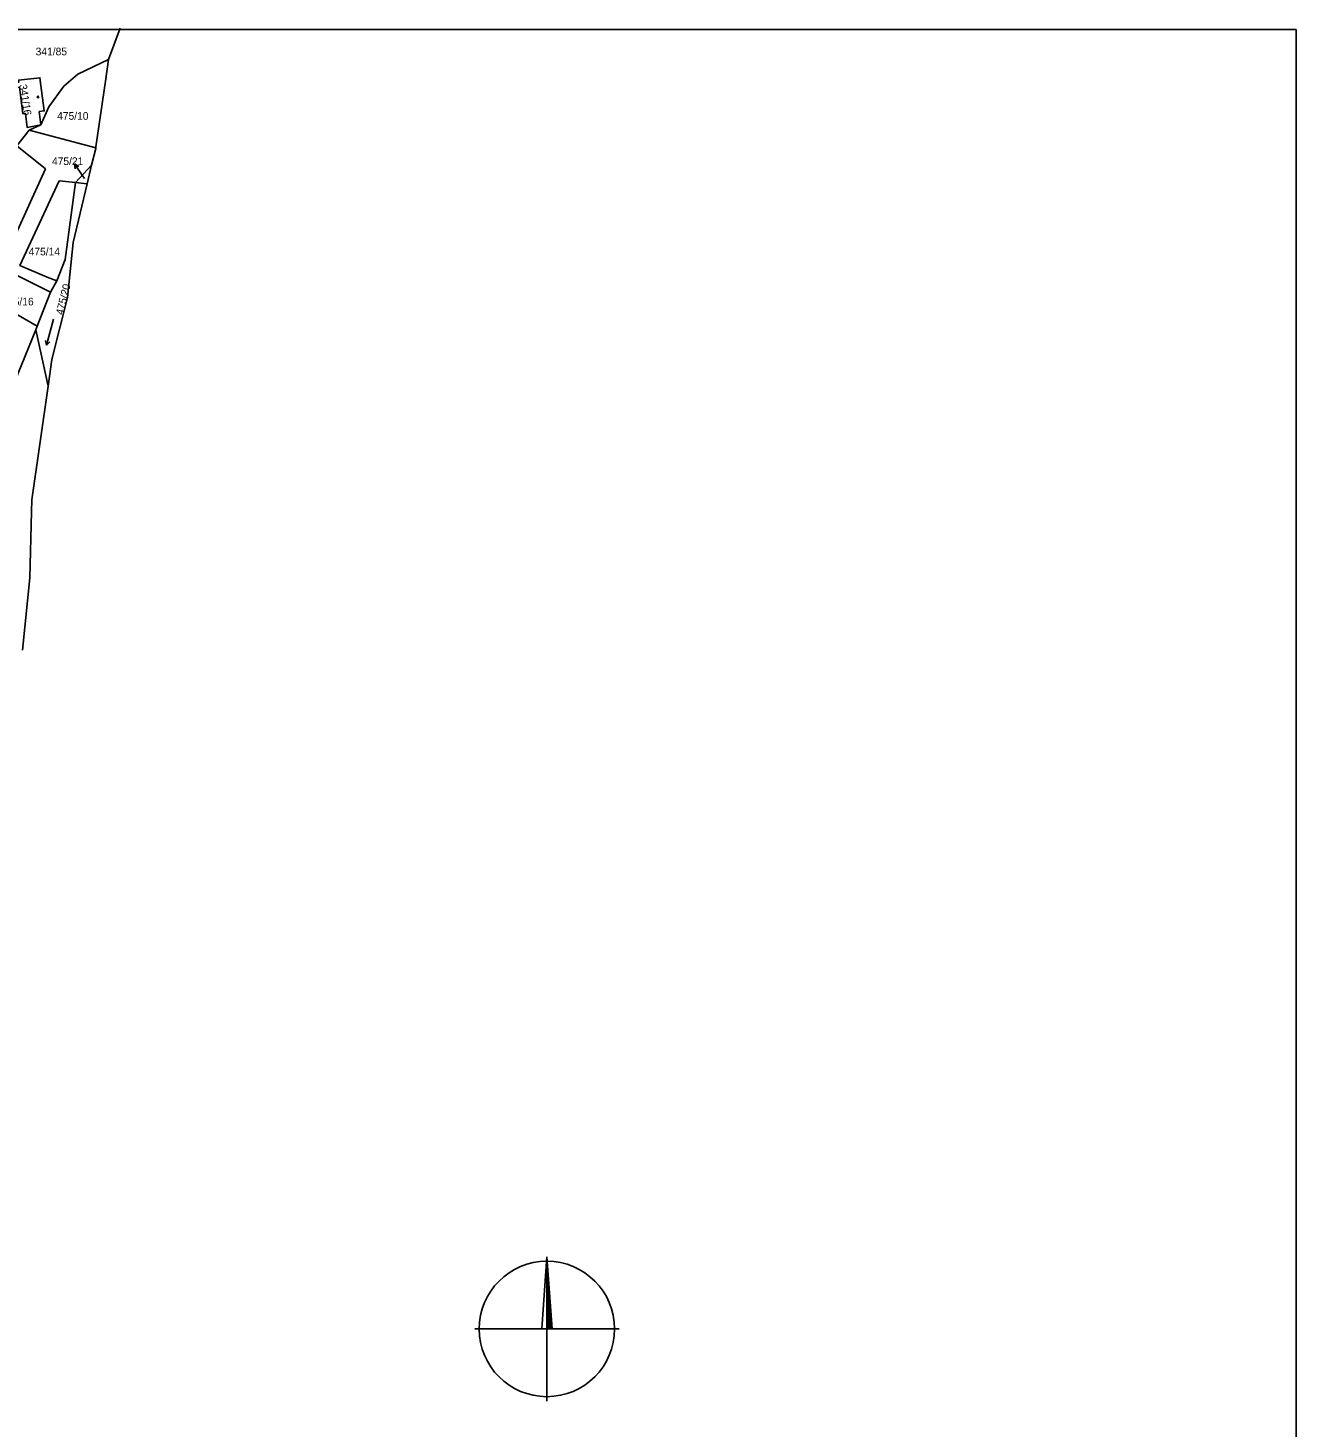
# Model space of a CAD drawing. Extents: x -558358 to -557517, y -1073786 to -1073189.
# Drawn here: x -557797.5 to -557516.5, y -1073499.8 to -1073189.7 of the extents above; entities that cross this region are included whole.
import ezdxf

# ---------------------------------------------------------------- set-up
doc = ezdxf.new("R2010")
doc.units = 0
for name, color, linetype in [('Hranice parcel', 7, 'Continuous'), ('Parcelní čísla', 7, 'Continuous'), ('Pop  PČ popisy', 7, 'Continuous'), ('Vrstva 1', 7, 'Continuous'), ('Značky budov', 7, 'Continuous'), ('Značky kultur', 7, 'Continuous')]:
    doc.layers.add(name, color=color, linetype=linetype)

msp = doc.modelspace()

# ---------------------------------------------------------------- linework, layer by layer
at = {"layer": 'Hranice parcel'}
for p, q in [((-557780.35, -1073201.52), (-557779.66, -1073196.74)), ((-557782.46, -1073216.02), (-557780.35, -1073201.52)), ((-557794.69, -1073211.15), (-557797.26, -1073212.4)), ((-557797.26, -1073212.4), (-557799.96, -1073215.86)), ((-557782.49, -1073216.26), (-557797.26, -1073212.4)), ((-557782.49, -1073216.26), (-557782.46, -1073216.02)), ((-557786.97, -1073223.95), (-557783.4, -1073220.15)), ((-557784.37, -1073224.22), (-557783.4, -1073220.15)), ((-557784.37, -1073224.22), (-557786.97, -1073223.95)), ((-557795.47, -1073255.77), (-557792.5, -1073248.24)), ((-557792.5, -1073248.24), (-557791.11, -1073245.75)), ((-557795.47, -1073255.77), (-557805.42, -1073250.06)), ((-557802.11, -1073272.13), (-557795.8, -1073256.6)), ((-557795.8, -1073256.6), (-557795.47, -1073255.77)), ((-557793.06, -1073269.04), (-557795.8, -1073256.6)), ((-557796.66, -1073294.23), (-557793.06, -1073269.04))]:
    msp.add_line(p, q, dxfattribs=at)
for points in [[(-557779.66, -1073196.74), (-557777.06, -1073189.74)], [(-557779.66, -1073196.74), (-557786.44, -1073199.97), (-557789.57, -1073202.65), (-557792.87, -1073207.17), (-557794.69, -1073211.15)], [(-557794.69, -1073211.15), (-557795, -1073208.24), (-557793.89, -1073208.1), (-557794.86, -1073200.76), (-557799.62, -1073201.3), (-557799.56, -1073201.75), (-557800.39, -1073201.86)], [(-557800.69, -1073202.99), (-557799.42, -1073202.82), (-557798.62, -1073208.73), (-557798.08, -1073208.66), (-557797.7, -1073211.74), (-557794.69, -1073211.15)], [(-557799.96, -1073215.86), (-557793.64, -1073220.96), (-557801.34, -1073237.87)], [(-557783.4, -1073220.15), (-557782.51, -1073216.43), (-557782.49, -1073216.26)], [(-557791.11, -1073245.75), (-557793.29, -1073244.89), (-557799.3, -1073242.34), (-557790.59, -1073223.57), (-557786.97, -1073223.95)], [(-557793.06, -1073269.04), (-557792.22, -1073263.19), (-557788.74, -1073249.45), (-557787.48, -1073237.23), (-557784.37, -1073224.22)], [(-557791.11, -1073245.75), (-557789.25, -1073241.02), (-557786.97, -1073223.95)], [(-557805.42, -1073250.06), (-557802.52, -1073245.72), (-557800.36, -1073244.34), (-557792.5, -1073248.24)], [(-557798.75, -1073327.52), (-557797.09, -1073311.5), (-557796.72, -1073296.93), (-557796.66, -1073294.23)]]:
    msp.add_lwpolyline(points, dxfattribs=at)
at = {"layer": 'Pop  PČ popisy'}
for p, q in [((-557785.49, -1073222.3), (-557787.21, -1073219.84)), ((-557787.21, -1073219.84), (-557786.23, -1073220.38)), ((-557787.21, -1073219.84), (-557787.05, -1073220.95)), ((-557784.97, -1073223.04), (-557785.49, -1073222.3))]:
    msp.add_line(p, q, dxfattribs=at)
at = {"layer": 'Vrstva 1'}
for p, q in [((-558357.53, -1073190.09), (-557516.53, -1073190.09)), ((-557516.53, -1073190.09), (-557516.53, -1073784.09)), ((-557682.53, -1073461.88), (-557683.68, -1073477.88)), ((-557682.53, -1073461.88), (-557681.35, -1073477.88)), ((-557682.53, -1073461.88), (-557682.53, -1073493.88)), ((-557682.43, -1073464.12), (-557681.46, -1073477.78)), ((-557682.4, -1073477.74), (-557682.43, -1073464.12)), ((-557682.36, -1073466.35), (-557681.56, -1073477.71)), ((-557682.29, -1073477.64), (-557682.36, -1073466.35)), ((-557682.26, -1073468.93), (-557681.66, -1073477.57)), ((-557682.22, -1073477.57), (-557682.26, -1073468.93)), ((-557682.15, -1073471.61), (-557681.77, -1073477.46)), ((-557682.12, -1073477.5), (-557682.15, -1073471.61)), ((-557682.01, -1073474.61), (-557681.87, -1073477.29)), ((-557682.01, -1073477.39), (-557682.01, -1073474.61)), ((-557698.53, -1073477.88), (-557666.53, -1073477.88)), ((-557681.35, -1073477.88), (-557682.4, -1073477.74)), ((-557681.46, -1073477.78), (-557682.29, -1073477.64)), ((-557681.56, -1073477.71), (-557682.22, -1073477.57)), ((-557681.66, -1073477.57), (-557682.12, -1073477.5)), ((-557681.77, -1073477.46), (-557682.01, -1073477.39))]:
    msp.add_line(p, q, dxfattribs=at)
msp.add_circle((-557682.53, -1073477.88), 15, dxfattribs=at)
at = {"layer": 'Značky budov'}
msp.add_circle((-557795.31, -1073205.01), 0.175, dxfattribs=at)
at = {"layer": 'Značky kultur'}
for p, q in [((-557791.86, -1073254.23), (-557793.41, -1073260.02)), ((-557793.41, -1073260.02), (-557793.64, -1073258.95)), ((-557793.41, -1073260.02), (-557792.67, -1073259.21))]:
    msp.add_line(p, q, dxfattribs=at)

# ---------------------------------------------------------------- texts
at = {"layer": 'Parcelní čísla'}
for s, p in [('341/85', (-557795.81, -1073195.79)), ('475/10', (-557791.05, -1073210.06)), ('475/21', (-557792.2, -1073220.09)), ('475/14', (-557797.36, -1073240.1)), ('475/16', (-557803.2, -1073251.18))]:
    msp.add_text(s, height=1.7, dxfattribs=at).set_placement(p)
for s, rotation, p in [('341/16', 279, (-557799.46, -1073202.33)), ('475/20', 76, (-557789.74, -1073253.41))]:
    msp.add_text(s, height=1.7, rotation=rotation, dxfattribs=at).set_placement(p)

doc.saveas('drawing.dxf')
